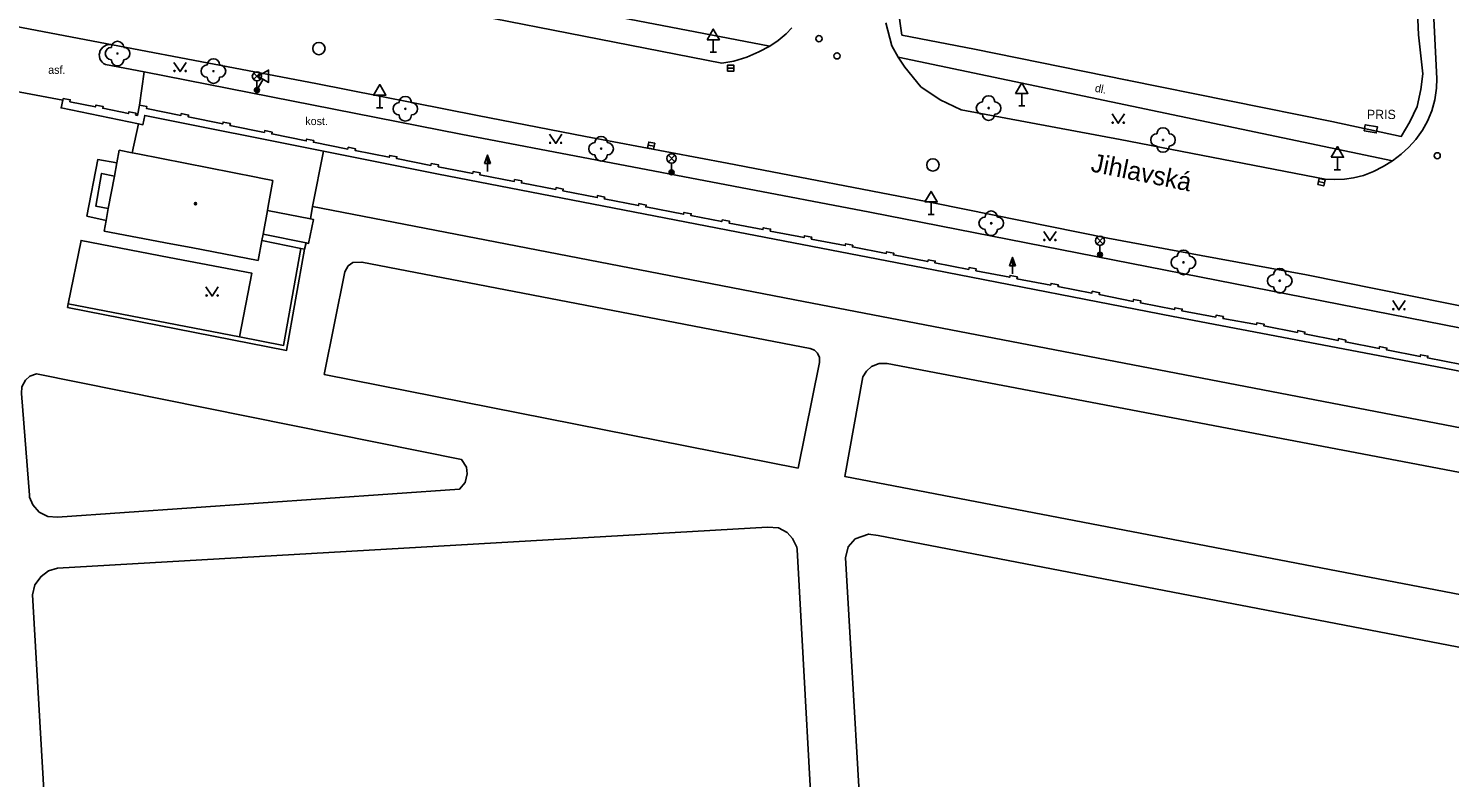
# Model space of a CAD drawing. Extents: x -599951 to -598963, y -1164095 to -1162939.
# Drawn here: x -599434.3 to -599318.9, y -1163192.8 to -1163132 of the extents above; entities that cross this region are included whole.
import ezdxf

# ---------------------------------------------------------------- set-up
doc = ezdxf.new("R2010")
doc.units = 0
for name, color, linetype in [('Level 10', 7, 'Continuous'), ('Level 11', 7, 'Continuous'), ('Level 22', 7, 'Continuous'), ('Level 24', 7, 'Continuous'), ('Level 25', 7, 'Continuous'), ('Level 27', 7, 'Continuous'), ('Level 28', 7, 'Continuous'), ('Level 33', 7, 'Continuous'), ('Level 34', 7, 'Continuous'), ('Level 36', 7, 'Continuous'), ('Level 39', 7, 'Continuous'), ('Level 40', 7, 'Continuous'), ('Level 41', 7, 'Continuous'), ('Level 49', 7, 'Continuous'), ('Level 5', 7, 'Continuous'), ('Level 54', 7, 'Continuous'), ('Level 7', 7, 'Continuous'), ('Level 8', 7, 'Continuous')]:
    doc.layers.add(name, color=color, linetype=linetype)

msp = doc.modelspace()

# ---------------------------------------------------------------- linework, layer by layer
at = {"layer": 'Level 10'}
for points in [[(-599319.94, -1163136.04), (-599325.34, -1163028.23)], [(-599413.29, -1163125.95), (-599412.3, -1163126.91), (-599410.82, -1163127.91), (-599408.99, -1163128.7), (-599378.01, -1163134.79)], [(-599364.69, -1163131.52), (-599364.2, -1163133.38)], [(-599427.48, -1163133.31), (-599435.87, -1163131.7)], [(-599374.09, -1163133.4), (-599373.41, -1163132.94), (-599372.77, -1163132.4), (-599372.3, -1163131.92)], [(-599300.49, -1163157.9), (-599316.16, -1163154.88), (-599330.52, -1163151.97), (-599339.06, -1163150.4), (-599346.64, -1163149), (-599360.7, -1163146.16), (-599377.57, -1163142.91), (-599389.08, -1163140.74), (-599397.83, -1163139.03), (-599410.97, -1163136.44), (-599427.48, -1163133.31)], [(-599375.97, -1163134.31), (-599374.98, -1163133.88), (-599374.09, -1163133.4)], [(-599364.2, -1163133.38), (-599363.68, -1163134.3)], [(-599378.01, -1163134.79), (-599377.03, -1163134.62), (-599375.97, -1163134.31)], [(-599363.68, -1163134.3), (-599363.13, -1163135.13)], [(-599363.13, -1163135.13), (-599361.84, -1163136.72)], [(-599320.35, -1163138.67), (-599320.1, -1163137.78), (-599319.96, -1163136.83), (-599319.94, -1163136.04)], [(-599361.84, -1163136.72), (-599360.27, -1163137.77)], [(-599360.27, -1163137.77), (-599358.56, -1163138.58)], [(-599329.01, -1163144.22), (-599345.66, -1163141), (-599358.56, -1163138.58)], [(-599321.64, -1163140.99), (-599321.09, -1163140.22), (-599320.69, -1163139.49), (-599320.35, -1163138.67)], [(-599323.53, -1163142.73), (-599322.84, -1163142.18), (-599322.21, -1163141.62), (-599321.64, -1163140.99)], [(-599325.88, -1163143.91), (-599325.08, -1163143.59), (-599324.28, -1163143.18), (-599323.53, -1163142.73)], [(-599329.01, -1163144.22), (-599328.24, -1163144.23), (-599327.43, -1163144.2)], [(-599327.43, -1163144.2), (-599326.7, -1163144.09), (-599325.88, -1163143.91)]]:
    msp.add_lwpolyline(points, dxfattribs=at)
at = {"layer": 'Level 11'}
for points in [[(-599374.09, -1163133.4), (-599395.55, -1163129.28), (-599413.29, -1163125.95)], [(-599428.05, -1163134.91), (-599428.2, -1163134.83), (-599428.32, -1163134.71), (-599428.42, -1163134.58), (-599428.5, -1163134.43), (-599428.54, -1163134.26), (-599428.55, -1163134.1), (-599428.52, -1163133.93), (-599428.5, -1163133.85), (-599428.47, -1163133.77), (-599428.38, -1163133.63), (-599428.27, -1163133.5), (-599428.13, -1163133.4), (-599427.98, -1163133.33), (-599427.81, -1163133.29), (-599427.65, -1163133.28), (-599427.48, -1163133.31)], [(-599424.9, -1163135.49), (-599428.05, -1163134.91)], [(-599323.53, -1163142.73), (-599363.68, -1163134.3)], [(-599424.9, -1163135.49), (-599425.28, -1163138.2)], [(-599316.59, -1163156.59), (-599365.98, -1163146.9), (-599399.18, -1163140.55), (-599424.9, -1163135.49)], [(-599425.87, -1163142.06), (-599425.37, -1163139.72)], [(-599411.23, -1163146.43), (-599410.34, -1163141.93)], [(-599428, -1163147.56), (-599429.55, -1163147.21), (-599428.68, -1163142.62), (-599427.13, -1163142.88)], [(-599427.82, -1163146.59), (-599428.82, -1163146.41), (-599428.36, -1163143.75), (-599427.33, -1163143.97)], [(-599411.23, -1163146.43), (-599411.41, -1163147.44)], [(-599250.18, -1163177.45), (-599371.36, -1163154.14), (-599411.23, -1163146.43)], [(-599414.9, -1163146.75), (-599411.41, -1163147.44)], [(-599411.41, -1163147.44), (-599411.15, -1163147.49), (-599411.56, -1163149.43), (-599411.76, -1163149.39)], [(-599411.76, -1163149.39), (-599415.25, -1163148.67)], [(-599431.09, -1163154.32), (-599430.03, -1163149.18), (-599422.88, -1163150.56), (-599416.16, -1163151.85), (-599417.17, -1163157)], [(-599415.34, -1163149.18), (-599412.19, -1163149.83)], [(-599411.76, -1163149.39), (-599411.89, -1163149.89)], [(-599371.81, -1163167.68), (-599410.29, -1163160.06), (-599408.61, -1163151.73), (-599408.35, -1163151.26), (-599407.97, -1163150.98), (-599407.23, -1163150.94), (-599370.83, -1163157.96), (-599370.46, -1163158.1), (-599370.23, -1163158.35), (-599370.06, -1163158.68), (-599370.06, -1163159.09), (-599371.81, -1163167.68)], [(-599304.68, -1163180.51), (-599368.02, -1163168.34), (-599366.56, -1163160.26), (-599366.26, -1163159.8), (-599365.83, -1163159.42), (-599365.22, -1163159.18), (-599364.57, -1163159.19), (-599304.36, -1163170.62)], [(-599433.64, -1163160.02), (-599399.13, -1163166.98), (-599398.74, -1163167.6), (-599398.67, -1163168.14), (-599398.85, -1163168.83), (-599399.29, -1163169.37), (-599431.94, -1163171.66), (-599432.73, -1163171.6), (-599433.44, -1163171.24), (-599433.96, -1163170.65), (-599434.21, -1163170.02), (-599434.23, -1163169.88), (-599434.86, -1163161.61), (-599434.84, -1163161.07), (-599434.54, -1163160.53), (-599434.18, -1163160.21), (-599433.64, -1163160.02)], [(-599431.95, -1163175.8), (-599374.29, -1163172.47), (-599373.39, -1163172.52), (-599372.7, -1163172.9), (-599372.25, -1163173.38), (-599371.92, -1163174.08), (-599371.88, -1163174.29), (-599370.28, -1163203.29)], [(-599366.31, -1163203.27), (-599367.96, -1163174.96), (-599367.74, -1163174.06), (-599367.16, -1163173.4), (-599366.08, -1163173.02), (-599365.31, -1163173.15)], [(-599365.31, -1163173.15), (-599306.33, -1163184.49), (-599305.52, -1163185.15), (-599305.14, -1163186.12), (-599304.34, -1163203.11)], [(-599433.32, -1163189.19), (-599433.97, -1163177.97), (-599433.78, -1163177.16), (-599433.28, -1163176.46), (-599432.67, -1163176.02), (-599431.95, -1163175.8)]]:
    msp.add_lwpolyline(points, dxfattribs=at)
at = {"layer": 'Level 22'}
for centre in [(-599427.07, -1163134.01), (-599419.28, -1163135.44), (-599403.7, -1163138.5), (-599356.33, -1163138.44), (-599387.8, -1163141.74), (-599342.17, -1163141.03), (-599356.12, -1163147.79), (-599340.51, -1163150.97), (-599332.69, -1163152.46)]:
    msp.add_circle(centre, 0.05, dxfattribs=at)
for centre, start, end in [((-599427.57, -1163134.01), 90, 270), ((-599427.07, -1163133.51), 0, 180), ((-599426.57, -1163134.01), 270, 90), ((-599427.07, -1163134.51), 180, 0), ((-599419.78, -1163135.44), 90, 270), ((-599419.28, -1163134.94), 0, 180), ((-599418.78, -1163135.44), 270, 90), ((-599419.28, -1163135.94), 180, 0), ((-599404.2, -1163138.5), 90, 270), ((-599403.7, -1163138), 0, 180), ((-599403.2, -1163138.5), 270, 90), ((-599356.83, -1163138.44), 90, 270), ((-599356.33, -1163137.94), 0, 180), ((-599355.83, -1163138.44), 270, 90), ((-599403.7, -1163139), 180, 0), ((-599356.33, -1163138.94), 180, 0), ((-599387.8, -1163141.24), 0, 180), ((-599342.67, -1163141.03), 90, 270), ((-599342.17, -1163140.53), 0, 180), ((-599341.67, -1163141.03), 270, 90), ((-599388.3, -1163141.74), 90, 270), ((-599387.3, -1163141.74), 270, 90), ((-599342.17, -1163141.53), 180, 0), ((-599387.8, -1163142.24), 180, 0), ((-599356.62, -1163147.79), 90, 270), ((-599356.12, -1163147.29), 0, 180), ((-599355.62, -1163147.79), 270, 90), ((-599356.12, -1163148.29), 180, 0), ((-599340.51, -1163150.47), 0, 180), ((-599341.01, -1163150.97), 90, 270), ((-599340.01, -1163150.97), 270, 90), ((-599340.51, -1163151.47), 180, 0), ((-599333.19, -1163152.46), 90, 270), ((-599332.69, -1163151.96), 0, 180), ((-599332.19, -1163152.46), 270, 90), ((-599332.69, -1163152.96), 180, 0)]:
    msp.add_arc(centre, 0.5, start, end, dxfattribs=at)
at = {"layer": 'Level 24'}
msp.add_lwpolyline([(-599325.84, -1163140.28), (-599324.85, -1163140.45), (-599324.76, -1163139.96), (-599325.75, -1163139.79)], close=True, dxfattribs=at)
at = {"layer": 'Level 25'}
for p, q in [((-599397.27, -1163142.94), (-599397.02, -1163142.26)), ((-599397.02, -1163142.94), (-599397.27, -1163142.94)), ((-599397.02, -1163143.59), (-599397.02, -1163142.94)), ((-599354.65, -1163151.24), (-599354.4, -1163150.56)), ((-599354.4, -1163151.24), (-599354.65, -1163151.24)), ((-599354.4, -1163151.89), (-599354.4, -1163151.24))]:
    msp.add_line(p, q, dxfattribs=at)
for points in [[(-599396.77, -1163142.94), (-599397.02, -1163142.94), (-599397.02, -1163142.26), (-599397.02, -1163142.26)], [(-599396.83, -1163142.9), (-599396.98, -1163142.9), (-599396.98, -1163142.49)], [(-599396.88, -1163142.86), (-599396.94, -1163142.86), (-599396.94, -1163142.71)], [(-599354.15, -1163151.24), (-599354.4, -1163151.24), (-599354.4, -1163150.56), (-599354.4, -1163150.56)], [(-599354.21, -1163151.2), (-599354.36, -1163151.2), (-599354.36, -1163150.79)], [(-599354.26, -1163151.16), (-599354.32, -1163151.16), (-599354.32, -1163151.01)]]:
    msp.add_lwpolyline(points, close=True, dxfattribs=at)
at = {"layer": 'Level 27'}
for p, q in [((-599377.53, -1163135.2), (-599377.03, -1163135.2)), ((-599383.98, -1163141.44), (-599383.5, -1163141.54)), ((-599329.55, -1163144.41), (-599329.07, -1163144.51))]:
    msp.add_line(p, q, dxfattribs=at)
for points in [[(-599377.53, -1163135.45), (-599377.03, -1163135.45), (-599377.03, -1163134.95), (-599377.53, -1163134.95)], [(-599384.03, -1163141.68), (-599383.55, -1163141.78), (-599383.45, -1163141.3), (-599383.93, -1163141.2)], [(-599329.61, -1163144.65), (-599329.12, -1163144.76), (-599329.01, -1163144.27), (-599329.5, -1163144.16)]]:
    msp.add_lwpolyline(points, close=True, dxfattribs=at)
for centre in [(-599410.72, -1163133.61), (-599360.86, -1163143.06)]:
    msp.add_circle(centre, 0.5, dxfattribs=at)
at = {"layer": 'Level 28'}
for centre in [(-599370.11, -1163132.81), (-599368.64, -1163134.2), (-599319.9, -1163142.31)]:
    msp.add_circle(centre, 0.25, dxfattribs=at)
at = {"layer": 'Level 33'}
for p, q in [((-599416.02, -1163136.12), (-599415.48, -1163135.59)), ((-599416.02, -1163135.59), (-599415.48, -1163136.12)), ((-599415.75, -1163136.23), (-599415.75, -1163136.98)), ((-599382.34, -1163142.8), (-599381.81, -1163142.27)), ((-599382.34, -1163142.27), (-599381.81, -1163142.8)), ((-599382.08, -1163142.91), (-599382.08, -1163143.66)), ((-599347.55, -1163149.48), (-599347.02, -1163148.95)), ((-599347.55, -1163148.95), (-599347.02, -1163149.48)), ((-599347.29, -1163149.59), (-599347.29, -1163150.34))]:
    msp.add_line(p, q, dxfattribs=at)
for centre, radius in [((-599415.75, -1163135.86), 0.375), ((-599415.75, -1163136.98), 0.2), ((-599415.75, -1163136.98), 0.145), ((-599415.75, -1163136.98), 0.0876), ((-599382.08, -1163142.53), 0.375), ((-599382.08, -1163143.66), 0.2), ((-599382.08, -1163143.66), 0.145), ((-599382.08, -1163143.66), 0.0876), ((-599347.29, -1163149.21), 0.375), ((-599347.29, -1163150.34), 0.2), ((-599347.29, -1163150.34), 0.145), ((-599347.29, -1163150.34), 0.0876)]:
    msp.add_circle(centre, radius, dxfattribs=at)
at = {"layer": 'Level 34'}
for p, q in [((-599378.69, -1163132.89), (-599378.69, -1163133.91)), ((-599378.94, -1163133.91), (-599378.44, -1163133.91)), ((-599415.24, -1163136.1), (-599415.75, -1163136.98)), ((-599415.97, -1163136.86), (-599415.53, -1163137.1)), ((-599353.64, -1163137.25), (-599353.64, -1163138.27)), ((-599406.03, -1163138.41), (-599405.53, -1163138.41)), ((-599405.78, -1163137.39), (-599405.78, -1163138.41)), ((-599353.89, -1163138.27), (-599353.39, -1163138.27)), ((-599328.01, -1163142.43), (-599328.01, -1163143.45)), ((-599328.26, -1163143.45), (-599327.76, -1163143.45)), ((-599361, -1163146.06), (-599361, -1163147.08)), ((-599361.25, -1163147.08), (-599360.75, -1163147.08))]:
    msp.add_line(p, q, dxfattribs=at)
for points in [[(-599379.19, -1163132.89), (-599378.19, -1163132.89), (-599378.69, -1163132.03)], [(-599415.68, -1163135.85), (-599414.81, -1163136.35), (-599414.81, -1163135.35)], [(-599406.28, -1163137.39), (-599405.28, -1163137.39), (-599405.78, -1163136.53)], [(-599354.14, -1163137.25), (-599353.14, -1163137.25), (-599353.64, -1163136.39)], [(-599328.51, -1163142.43), (-599327.51, -1163142.43), (-599328.01, -1163141.57)], [(-599361.5, -1163146.06), (-599360.5, -1163146.06), (-599361, -1163145.2)]]:
    msp.add_lwpolyline(points, close=True, dxfattribs=at)
at = {"layer": 'Level 36'}
for points in [[(-599422.49, -1163134.73), (-599421.99, -1163135.48), (-599421.49, -1163134.73)], [(-599346.31, -1163138.92), (-599345.81, -1163139.67), (-599345.31, -1163138.92)], [(-599391.99, -1163140.56), (-599391.49, -1163141.31), (-599390.99, -1163140.56)], [(-599351.86, -1163148.45), (-599351.36, -1163149.2), (-599350.86, -1163148.45)], [(-599419.89, -1163152.96), (-599419.39, -1163153.71), (-599418.89, -1163152.96)], [(-599323.51, -1163154.07), (-599323.01, -1163154.82), (-599322.51, -1163154.07)]]:
    msp.add_lwpolyline(points, dxfattribs=at)
for centre in [(-599422.44, -1163135.43), (-599421.54, -1163135.43), (-599346.26, -1163139.62), (-599345.36, -1163139.62), (-599391.94, -1163141.26), (-599391.04, -1163141.26), (-599351.81, -1163149.15), (-599350.91, -1163149.15), (-599419.84, -1163153.66), (-599418.94, -1163153.66), (-599323.46, -1163154.77), (-599322.56, -1163154.77)]:
    msp.add_circle(centre, 0.05, dxfattribs=at)
at = {"layer": 'Level 39'}
for radius in [0.09, 0.0398]:
    msp.add_circle((-599420.74, -1163146.2), radius, dxfattribs=at)
at = {"layer": 'Level 5'}
for points in [[(-599427.13, -1163142.88), (-599426.94, -1163141.85)], [(-599426.94, -1163141.85), (-599425.87, -1163142.06)], [(-599427.33, -1163143.97), (-599427.13, -1163142.88)], [(-599425.87, -1163142.06), (-599425.43, -1163142.15)], [(-599425.43, -1163142.15), (-599415.82, -1163144.06)], [(-599427.82, -1163146.59), (-599427.33, -1163143.97)], [(-599415.82, -1163144.06), (-599415.43, -1163144.14)], [(-599415.43, -1163144.14), (-599414.45, -1163144.33)], [(-599414.45, -1163144.33), (-599414.83, -1163146.39)], [(-599414.83, -1163146.39), (-599414.9, -1163146.75)], [(-599428.16, -1163148.42), (-599428, -1163147.56)], [(-599428, -1163147.56), (-599427.82, -1163146.59)], [(-599414.9, -1163146.75), (-599415.25, -1163148.67)], [(-599422.73, -1163149.45), (-599428.16, -1163148.42)], [(-599415.25, -1163148.67), (-599415.34, -1163149.18)], [(-599421.08, -1163149.77), (-599422.73, -1163149.45)], [(-599415.64, -1163150.81), (-599421.08, -1163149.77)], [(-599415.34, -1163149.18), (-599415.64, -1163150.81)]]:
    msp.add_lwpolyline(points, dxfattribs=at)
at = {"layer": 'Level 54'}
msp.add_lwpolyline([(-599430.45, -1163238.46), (-599433.32, -1163189.19)], dxfattribs=at)
at = {"layer": 'Level 7'}
for points in [[(-599321.42, -1163132.48), (-599321.08, -1163135.65), (-599321.23, -1163136.94), (-599321.52, -1163138.3), (-599322.12, -1163139.55), (-599322.83, -1163140.74), (-599328.47, -1163139.54), (-599345.08, -1163136.16), (-599357.48, -1163133.67), (-599363.37, -1163132.51), (-599363.71, -1163130.22), (-599364.09, -1163125.33), (-599367.01, -1163069.41)], [(-599322.56, -1163106.09), (-599321.42, -1163132.48)], [(-599425.37, -1163139.72), (-599431.65, -1163138.43), (-599431.52, -1163137.8)], [(-599431.52, -1163137.8), (-599431.49, -1163137.65)], [(-599425.28, -1163138.2), (-599425.45, -1163139.03), (-599425.6, -1163139), (-599425.57, -1163138.86), (-599426.15, -1163138.74), (-599426.18, -1163138.88), (-599428.27, -1163138.46), (-599428.24, -1163138.31), (-599428.83, -1163138.19), (-599428.86, -1163138.34), (-599430.94, -1163137.92), (-599430.91, -1163137.77), (-599431.49, -1163137.65)], [(-599377.97, -1163147.51), (-599378, -1163147.66), (-599380.51, -1163147.17), (-599380.48, -1163147.02), (-599381.07, -1163146.91), (-599381.1, -1163147.06), (-599384.17, -1163146.47), (-599384.14, -1163146.32), (-599384.73, -1163146.2), (-599384.76, -1163146.35), (-599387.54, -1163145.81), (-599387.51, -1163145.67), (-599388.1, -1163145.55), (-599388.12, -1163145.7), (-599390.9, -1163145.16), (-599390.88, -1163145.02), (-599391.46, -1163144.9), (-599391.49, -1163145.05), (-599394.27, -1163144.51), (-599394.24, -1163144.36), (-599394.83, -1163144.25), (-599394.86, -1163144.4), (-599397.64, -1163143.86), (-599397.61, -1163143.71), (-599398.2, -1163143.6), (-599398.23, -1163143.75), (-599401.03, -1163143.2), (-599401, -1163143.05), (-599401.59, -1163142.94), (-599401.62, -1163143.09), (-599404.41, -1163142.54), (-599404.38, -1163142.39), (-599404.97, -1163142.28), (-599405, -1163142.43), (-599407.78, -1163141.88), (-599407.75, -1163141.74), (-599408.34, -1163141.62), (-599408.37, -1163141.77), (-599411.16, -1163141.22), (-599411.13, -1163141.08), (-599411.72, -1163140.96), (-599411.75, -1163141.11), (-599414.55, -1163140.54), (-599414.52, -1163140.39), (-599415.11, -1163140.27), (-599415.14, -1163140.42), (-599417.94, -1163139.85), (-599417.91, -1163139.7), (-599418.5, -1163139.58), (-599418.53, -1163139.73), (-599421.33, -1163139.16), (-599421.3, -1163139.01), (-599421.89, -1163138.89), (-599421.92, -1163139.04), (-599424.72, -1163138.47), (-599424.69, -1163138.32), (-599425.28, -1163138.2)], [(-599410.34, -1163141.93), (-599424.86, -1163139.03), (-599425.01, -1163139.79), (-599425.37, -1163139.72)], [(-599245.2, -1163174.96), (-599246.21, -1163173.61), (-599265.54, -1163169.93), (-599283.2, -1163166.52), (-599297.25, -1163163.77), (-599310.76, -1163161.2), (-599324.13, -1163158.64), (-599341.34, -1163155.37), (-599360.8, -1163151.58), (-599377.52, -1163148.34), (-599401.14, -1163143.77), (-599410.34, -1163141.93)], [(-599361.25, -1163150.75), (-599361.28, -1163150.9), (-599364.06, -1163150.36), (-599364.03, -1163150.21), (-599364.62, -1163150.1), (-599364.65, -1163150.24), (-599367.39, -1163149.71), (-599367.37, -1163149.57), (-599367.95, -1163149.45), (-599367.98, -1163149.6), (-599370.73, -1163149.07), (-599370.7, -1163148.92), (-599371.29, -1163148.8), (-599371.32, -1163148.95), (-599374.07, -1163148.42), (-599374.04, -1163148.27), (-599374.63, -1163148.16), (-599374.66, -1163148.3), (-599377.41, -1163147.77), (-599377.38, -1163147.62), (-599377.97, -1163147.51)], [(-599411.89, -1163149.89), (-599413.34, -1163158.11), (-599431.13, -1163154.63), (-599431.09, -1163154.32)], [(-599417.17, -1163157), (-599413.59, -1163157.71), (-599412.19, -1163149.83)], [(-599412.19, -1163149.83), (-599411.89, -1163149.89)], [(-599347.91, -1163153.31), (-599347.94, -1163153.46), (-599350.7, -1163152.93), (-599350.67, -1163152.78), (-599351.26, -1163152.67), (-599351.29, -1163152.81), (-599354.03, -1163152.29), (-599354, -1163152.14), (-599354.59, -1163152.03), (-599354.62, -1163152.18), (-599357.36, -1163151.65), (-599357.33, -1163151.5), (-599357.92, -1163151.39), (-599357.95, -1163151.54), (-599360.69, -1163151.01), (-599360.66, -1163150.86), (-599361.25, -1163150.75)], [(-599317.92, -1163159.26), (-599320.69, -1163158.72), (-599320.66, -1163158.57), (-599321.25, -1163158.46), (-599321.28, -1163158.61), (-599324.02, -1163158.07), (-599323.99, -1163157.93), (-599324.58, -1163157.81), (-599324.61, -1163157.96), (-599327.36, -1163157.42), (-599327.33, -1163157.27), (-599327.92, -1163157.16), (-599327.95, -1163157.31), (-599330.67, -1163156.78), (-599330.64, -1163156.63), (-599331.23, -1163156.51), (-599331.26, -1163156.66), (-599333.98, -1163156.13), (-599333.95, -1163155.99), (-599334.54, -1163155.87), (-599334.57, -1163156.02), (-599337.3, -1163155.52), (-599337.27, -1163155.37), (-599337.86, -1163155.26), (-599337.89, -1163155.41), (-599340.64, -1163154.91), (-599340.61, -1163154.76), (-599341.2, -1163154.65), (-599341.23, -1163154.8), (-599344, -1163154.24), (-599343.97, -1163154.1), (-599344.56, -1163153.98), (-599344.59, -1163154.13), (-599347.35, -1163153.58), (-599347.32, -1163153.43), (-599347.91, -1163153.31)], [(-599431.09, -1163154.32), (-599417.17, -1163157)]]:
    msp.add_lwpolyline(points, dxfattribs=at)
at = {"layer": 'Level 8'}
msp.add_lwpolyline([(-599431.52, -1163137.8), (-599435.84, -1163136.99)], dxfattribs=at)

# ---------------------------------------------------------------- texts
at = {"layer": 'Level 40'}
for s, p in [('asf.', (-599432.7, -1163135.66)), ('kost.', (-599411.82, -1163139.82))]:
    msp.add_text(s, height=0.65, dxfattribs=at).set_placement(p)
msp.add_text('dl.', height=0.65, rotation=348.61, dxfattribs=at).set_placement((-599347.74, -1163137.1))
at = {"layer": 'Level 41'}
msp.add_text('PRIS', height=0.75, dxfattribs=at).set_placement((-599325.61, -1163139.33))
at = {"layer": 'Level 49'}
msp.add_text('Jihlavská', height=1.5, rotation=348.5, dxfattribs=at).set_placement((-599348.11, -1163143.57))

doc.saveas('drawing.dxf')
